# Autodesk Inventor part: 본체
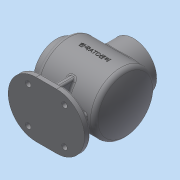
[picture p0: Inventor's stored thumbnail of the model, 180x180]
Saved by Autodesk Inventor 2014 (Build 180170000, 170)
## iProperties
Created: 2023-01
Part Number: 본체
Material: 일반
Document SubType Name: Modeling
Designer: dg
Density: 1 g/cm^3
Appearance: 기본값
Author: dg
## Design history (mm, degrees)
sketch "스케치1"
  geometry: L1 (0, 0)-(122, 0); L2 (0, 0)-(0, 38); L3 (0, 38)-(12, 38); L4 (12, 38)-(12, 50); L5 (12, 50)-(111.087, 50); L6 (107.83, 45)-(17, 45); L7 (17, 45)-(17, 27); L8 (17, 27)-(0, 27); A1 r 120 centre (2, 0) between (122, 0) and (111.087, 50); A2 r 115 centre (2, 0) between (117, 0) and (107.83, 45)
  constraints: 16 end point, 4 point on circle, 2 centre point, 2 horizontal, 2 perpendicular, 2 point on line, 1 horizontal alignment, 1 parallel, 1 other
  dimensions: "d0" = 122 distance of L1.start L1.end; "d1" = 110 distance from line of L1.end L4; "d2" = 76 diameter of L3 L1; "d3" = 100 diameter of L5 L1; "d4" = 120 radius of A1; "d5" = 54 diameter of L8 L1; "d6" = 5 radial gap between concentric circles of A1 A2; "d7" = 90 diameter of L6 L1
revolve "회전1" sketch "스케치1" stored, may be unused: angle "d8" = 90 deg
node "작업 평면1"
sketch "스케치2"
  geometry: L1 (-46, 0)-(-80, 0); L2 (-46, 46)-(-80, 46); L3 (-80, -46)-(-46, -46); A1 r 46 centre (-46, 0) between (-46, -46) and (-46, 46); A2 r 46 centre (-80, 0) between (-80, 46) and (-80, -46); 4 further points
  constraints: 8 end point, 6 point on circle, 4 tangent, 2 centre point, 2 coincident, 1 horizontal, 1 horizontal alignment, 1 midpoint, 1 parallel
  dimensions: "d10" = 126 distance of point (-126, 0) point (0, 0); "d11" = 92 distance between parallel lines of L3 L2
extrude "돌출1" join sketch "스케치2" distance "d12" = 10; taper "d13" = 0 deg
node "작업 평면2"
sketch "스케치3"
  geometry: L1 (-80, 46)-(-70, 46) reference; L2 (-70, 46)-(-70, -46) reference; L3 (-70, -46)-(-80, -46) reference; L4 (-80, -46)-(-80, 46) reference; L5 (-35.707, 35)-(-70, 35); L6 (-35.707, -35)-(-70, -35); C1 r 45 at (0, 0) reference; A1 r 50 centre (0, 0) between (-35.707, 35) and (-35.707, -35) reference; 1 further point
  constraints: 4 end point, 2 perpendicular, 2 point on circle, 2 point on line, 1 parallel
  dimensions: "d15" = 70 distance between parallel lines of L6 L5
extrude "돌출2" join sketch "스케치3" stored distance "d16" = 10; taper "d17" = 0 deg
node "작업 평면3"
sketch "스케치4"
  geometry: L1 (107.83, 45)-(17, 45) reference; L2 (17, 45)-(17, 27) reference; L3 (17, 27)-(0, 27) reference; L4 (0, 27)-(0, 38) reference; L5 (0, 38)-(12, 38) reference; L6 (12, 38)-(12, 50) reference; L7 (12, 50)-(111.087, 50) reference; L8 (111.087, -50)-(68, -50) reference; L9 (68, -50)-(68, -70) reference; L10 (68, -70)-(126, -70) reference; L11 (126, -70)-(126, -80) reference; L12 (126, -80)-(0, -80) reference; L13 (0, -80)-(0, -70) reference; L14 (0, -70)-(58, -70) reference; L15 (58, -70)-(58, -50) reference; L16 (58, -50)-(12, -50) reference; L17 (12, -50)-(12, -38) reference; L18 (12, -38)-(0, -38) reference; L19 (0, -38)-(0, -27) reference; L20 (0, -27)-(17, -27) reference; L21 (17, -27)-(17, -45) reference; L22 (17, -45)-(107.83, -45) reference; L23 (28.359, -50)-(23, -70); L24 (97.641, -50)-(103, -70); A1 r 115 centre (2, 0) between (107.83, -45) and (107.83, 45) reference; A2 r 120 centre (2, 0) between (111.087, -50) and (111.087, 50) reference; 1 further point
  constraints: 4 end point, 4 point on line, 1 equal length
  dimensions: "d19" = 23 distance from line of L13 L23.end; "d20" = 105 deg angle of L14 L23; "d21" = 80 distance of L24.end L23.end
  node "절단 모서리 투영2"
feature "리브1" dims "d22" = 1, "d23" = 10, "d24" = 0, "d25" = 0, "d26" = 1, "d27" = 1
feature "리브2" dims "d28" = 1, "d29" = 10, "d30" = 0, "d31" = 0, "d32" = 1, "d33" = 1
node "작업 평면4"
sketch "스케치5"
  geometry: L1 (-12, 50)-(-12, -50) reference; C1 r 38 at (-63, 0); 1 further point
  constraints: 1 centre point, 1 horizontal alignment
  dimensions: "d35" = 51 distance from line of L1 C1.centre; "d36" = 76 diameter of C1
extrude "돌출3" join sketch "스케치5" stored distance "d37" = 10; taper "d38" = 0 deg
sketch "스케치6"
  geometry: C1 r 38 at (0, 0) reference; 2 further points
  constraints: 1 coincident
hole "구멍1" sketch "스케치6" at (0, 0) diameter "d39" = 54; stored, may be unused: countersink angle "d43" = 90 deg, drill point angle "d45" = 118 deg; dims "d40" = 6, "d41" = 4, "d42" = 2, "d44" = 8
sketch "스케치7"
  geometry: C1 r 38 at (0, 0) reference; 1 further point
  constraints: 1 vertical alignment
  dimensions: "d46" = 32.5 distance of C1.centre point (0, 32.5)
hole "구멍2" sketch "스케치7" at (0, 32.5) diameter "d47" = 3.242; stored, may be unused: countersink angle "d51" = 90 deg, drill point angle "d53" = 118 deg; dims "d48" = 8, "d49" = 4, "d50" = 2, "d52" = 10
sketch "스케치8"
  geometry: C1 r 27 at (0, 0) reference; 2 further points
  constraints: 1 vertical alignment
  dimensions: "d57" = 32.5 distance of C1.centre point (0, 32.5)
hole "구멍3" sketch "스케치8" at (0, 32.5) diameter "d58" = 3.242; stored, may be unused: countersink angle "d62" = 90 deg, drill point angle "d64" = 118 deg; dims "d59" = 8, "d60" = 4, "d61" = 2, "d63" = 10
sketch "스케치9"
  geometry: L1 (58, -5)-(23, -5) reference; L2 (58, 5)-(58, 35) reference; 5 further points
  constraints: 2 horizontal alignment, 2 vertical alignment
  dimensions: "d68" = 60 distance of point (93, 30) point (33, 30); "d69" = 60 distance of point (33, 30) point (33, -30); "d70" = 25 distance from line of L2 point (33, 30); "d71" = 25 distance from line of L1 point (33, -30)
hole "구멍4" sketch "스케치9" at (33, 30), (93, 30), (93, -30), (33, -30) diameter "d72" = 9; stored, may be unused: countersink angle "d76" = 90 deg, drill point angle "d78" = 118 deg; dims "d73" = 8, "d74" = 4, "d75" = 2, "d77" = 10
fillet "모깎기1" dims "d79" = 8
fillet "모깎기2" dims "d80" = 3
fillet "모깎기3" dims "d81" = 3
chamfer "모따기1" distance "d82" = 1; stored, may be unused: second distance "d83" = 2, angle "d84" = 45 deg
fillet "모깎기4" dims "d85" = 3
fillet "모깎기5" dims "d86" = 3
node "작업 평면5"
sketch "스케치10"
  geometry: L1 (-41.544, 0)-(44.283, 0) reference; L2 (-61.544, -38)-(-61.544, 38) reference; L3 (64.456, -80)-(18.456, -80) reference; 2 further points
  constraints: 1 other
  dimensions: "d87" = 63 distance from line of L2 point (1.456, 0); "d88" = 80 distance from line of L3 point (1.456, 0)
feature "엠보싱1" sketch "스케치10" dims "d89" = 0.5, "d90" = 0
node "솔리드1"
pattern_circular "원형 패턴1" dims angle "d55" = 360 deg
pattern_circular "원형 패턴2" dims angle "d66" = 360 deg
node "절단 모서리 투영1"
node "절단 모서리 투영3"
other parameters: "d14" = 63, "d18" = 0, "d34" = 144
